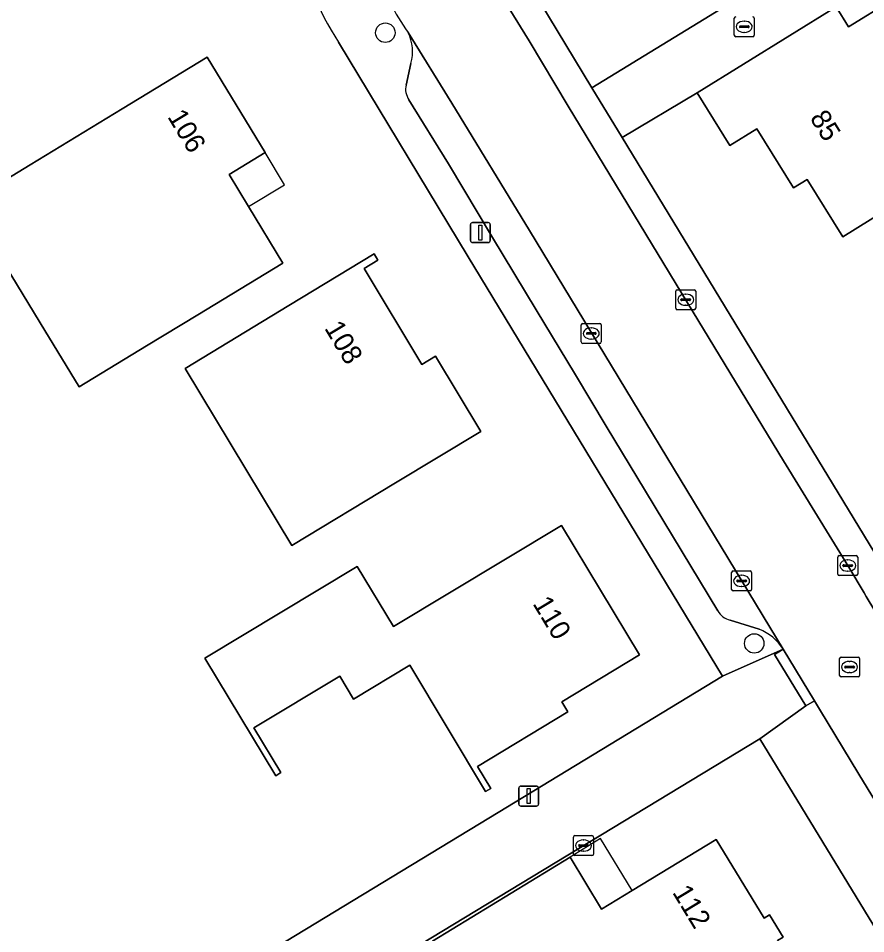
# Model space of a CAD drawing. Extents: x 157767 to 159172, y 387839 to 389425.
# Drawn here: x 158027.91 to 158070.43, y 388633.65 to 388679.57 of the extents above; entities that cross this region are included whole.
import ezdxf

# ---------------------------------------------------------------- set-up
doc = ezdxf.new("R2010")
doc.units = 0
for name, color, linetype in [('IMGEO_Boom', 7, 'Continuous'), ('IMGEO_Erf', 7, 'Continuous'), ('IMGEO_Kolk', 7, 'Continuous'), ('IMGEO_Lichtmast', 7, 'Continuous'), ('IMGEO_Muur', 7, 'Continuous'), ('IMGEO_Pand', 7, 'Continuous'), ('IMGEO_Pand_nummerreeks', 7, 'Continuous'), ('IMGEO_Pand_overbouw', 7, 'Continuous'), ('IMGEO_Parkeervlak_open', 7, 'Continuous'), ('IMGEO_Rijbaan_lokaal_open', 7, 'Continuous'), ('IMGEO_Rioolput', 7, 'Continuous'), ('IMGEO_Voetpad_open', 7, 'Continuous')]:
    doc.layers.add(name, color=color, linetype=linetype)

msp = doc.modelspace()

# ---------------------------------------------------------------- linework, layer by layer
at = {"layer": 'IMGEO_Boom'}
for centre in [(158046.326, 388678.85), (158064.837, 388648.212)]:
    msp.add_circle(centre, 0.489, dxfattribs=at)
at = {"layer": 'IMGEO_Erf'}
for points in [[(158052.773, 388682.571), (158056.692, 388676.089), (158064.654, 388680.973)], [(158068.943, 388680.157), (158069.57, 388679.146), (158073.821, 388681.779), (158076.455, 388677.529), (158077.139, 388676.424), (158076.034, 388675.74), (158077.06, 388674.085), (158076.816, 388673.284), (158073.526, 388671.246), (158069.275, 388668.613), (158067.496, 388671.486), (158066.81, 388671.062), (158064.973, 388674.028), (158063.613, 388673.186), (158061.971, 388675.839), (158058.217, 388673.595), (158071.632, 388651.501), (158075.819, 388644.604), (158080.893, 388635.943)], [(158027.097, 388624.476), (158029.051, 388625.711), (158032.676, 388628.003), (158051.995, 388639.731), (158063.248, 388646.562), (158050.482, 388667.602), (158043.974, 388678.374)], [(158073.538, 388629.633), (158065.111, 388643.432), (158048.605, 388633.424), (158041.934, 388629.381), (158019.422, 388615.682), (158006.062, 388607.391), (158003.544, 388605.795), (158007.121, 388599.66), (158008.464, 388601.21), (158008.786, 388601.467), (158010.188, 388602.586), (158011.828, 388603.703), (158014.005, 388604.812), (158016.147, 388601.216), (158027.188, 388581.174), (158029.267, 388577.665), (158033.868, 388570.534), (158041.859, 388557.406), (158043.338, 388554.813), (158043.765, 388552.918), (158061.703, 388519.687), (158072.331, 388500), (158089.66, 388467.898), (158102.446, 388447.213)]]:
    msp.add_lwpolyline(points, dxfattribs=at)
for points in [[(158037.39, 388677.63), (158040.29, 388672.84), (158038.486, 388671.746), (158039.466, 388670.129), (158041.187, 388667.29), (158036.912, 388664.699), (158034.35, 388663.146), (158030.958, 388661.09), (158029.242, 388663.909), (158025.35, 388670.303), (158028.5, 388672.22), (158033.119, 388675.031)], [(158051.122, 388658.843), (158046.84, 388656.263), (158041.631, 388653.124), (158036.277, 388662.007), (158041.486, 388665.171), (158045.759, 388667.766), (158045.955, 388667.439), (158045.269, 388667.028), (158048.164, 388662.21), (158048.851, 388662.622)], [(158055.159, 388654.135), (158059.082, 388647.632), (158055.181, 388645.285), (158055.488, 388644.772), (158050.953, 388642.044), (158051.617, 388640.94), (158051.36, 388640.786), (158047.552, 388647.116), (158044.729, 388645.417), (158044.038, 388646.563), (158039.735, 388643.974), (158041.083, 388641.732), (158040.826, 388641.577), (158037.274, 388647.48), (158044.921, 388652.079), (158046.732, 388649.068)], [(158051.48, 388628.668), (158051.278, 388629.002), (158048.692, 388633.28), (158055.594, 388637.493), (158057.18, 388634.883), (158058.716, 388635.816), (158062.929, 388638.376), (158065.328, 388634.427), (158065.602, 388634.594), (158066.281, 388633.476), (158066.009, 388633.312), (158066.589, 388632.357), (158062.319, 388629.758), (158057.749, 388626.976), (158055.323, 388630.99)]]:
    msp.add_lwpolyline(points, close=True, dxfattribs=at)
msp.add_arc((158058.394, 388687.505), 17.068, 174.4587, 212.3421, dxfattribs=at)
at = {"layer": 'IMGEO_Kolk'}
for p, q in [((158063.835, 388678.722), (158063.835, 388679.574)), ((158064.836, 388679.574), (158064.836, 388678.722)), ((158064.094, 388679.142), (158064.094, 388679.154)), ((158064.532, 388679.105), (158064.134, 388679.105)), ((158064.137, 388679.191), (158064.535, 388679.191)), ((158064.323, 388679.428), (158064.348, 388679.428)), ((158064.578, 388679.154), (158064.578, 388679.142)), ((158064.762, 388678.648), (158063.91, 388678.648)), ((158064.346, 388678.868), (158064.321, 388678.868)), ((158060.899, 388665.029), (158060.899, 388665.881)), ((158060.974, 388665.955), (158061.826, 388665.955)), ((158061.387, 388665.735), (158061.412, 388665.735)), ((158061.9, 388665.881), (158061.9, 388665.029)), ((158061.158, 388665.449), (158061.158, 388665.461)), ((158061.596, 388665.412), (158061.198, 388665.412)), ((158061.201, 388665.498), (158061.599, 388665.498)), ((158061.642, 388665.461), (158061.642, 388665.449)), ((158061.826, 388664.955), (158060.974, 388664.955)), ((158061.41, 388665.175), (158061.385, 388665.175)), ((158056.159, 388663.336), (158056.159, 388664.188)), ((158056.234, 388664.262), (158057.086, 388664.262)), ((158056.647, 388664.042), (158056.672, 388664.042)), ((158057.16, 388664.188), (158057.16, 388663.336)), ((158056.418, 388663.756), (158056.418, 388663.768)), ((158056.856, 388663.719), (158056.458, 388663.719)), ((158056.461, 388663.805), (158056.859, 388663.805)), ((158056.67, 388663.482), (158056.645, 388663.482)), ((158056.902, 388663.768), (158056.902, 388663.756)), ((158057.086, 388663.262), (158056.234, 388663.262)), ((158069.027, 388651.692), (158069.027, 388652.544)), ((158069.102, 388652.618), (158069.954, 388652.618)), ((158069.515, 388652.398), (158069.54, 388652.398)), ((158070.028, 388652.544), (158070.028, 388651.692)), ((158069.286, 388652.112), (158069.286, 388652.124)), ((158069.724, 388652.075), (158069.326, 388652.075)), ((158069.329, 388652.161), (158069.727, 388652.161)), ((158069.77, 388652.124), (158069.77, 388652.112)), ((158063.702, 388650.923), (158063.702, 388651.775)), ((158063.777, 388651.849), (158064.629, 388651.849)), ((158064.19, 388651.629), (158064.215, 388651.629)), ((158064.703, 388651.775), (158064.703, 388650.923)), ((158069.954, 388651.618), (158069.102, 388651.618)), ((158069.538, 388651.838), (158069.513, 388651.838)), ((158063.961, 388651.343), (158063.961, 388651.355)), ((158064.399, 388651.306), (158064.001, 388651.306)), ((158064.004, 388651.392), (158064.402, 388651.392)), ((158064.213, 388651.069), (158064.188, 388651.069)), ((158064.445, 388651.355), (158064.445, 388651.343)), ((158064.629, 388650.849), (158063.777, 388650.849)), ((158055.768, 388637.646), (158055.768, 388638.498)), ((158055.843, 388638.572), (158056.695, 388638.572)), ((158056.256, 388638.352), (158056.281, 388638.352)), ((158056.769, 388638.498), (158056.769, 388637.646)), ((158056.027, 388638.066), (158056.027, 388638.078)), ((158056.465, 388638.029), (158056.067, 388638.029)), ((158056.07, 388638.115), (158056.468, 388638.115)), ((158056.279, 388637.792), (158056.254, 388637.792)), ((158056.511, 388638.078), (158056.511, 388638.066)), ((158056.695, 388637.572), (158055.843, 388637.572))]:
    msp.add_line(p, q, dxfattribs=at)
for points in [[(158063.835, 388678.722), (158063.835, 388679.574)], [(158064.836, 388679.574), (158064.836, 388678.722)], [(158064.762, 388678.648), (158063.91, 388678.648)], [(158060.899, 388665.029), (158060.899, 388665.881)], [(158060.974, 388665.955), (158061.826, 388665.955)], [(158061.9, 388665.881), (158061.9, 388665.029)], [(158061.826, 388664.955), (158060.974, 388664.955)], [(158056.159, 388663.336), (158056.159, 388664.188)], [(158056.234, 388664.262), (158057.086, 388664.262)], [(158057.16, 388664.188), (158057.16, 388663.336)], [(158057.086, 388663.262), (158056.234, 388663.262)], [(158069.027, 388651.692), (158069.027, 388652.544)], [(158069.102, 388652.618), (158069.954, 388652.618)], [(158070.028, 388652.544), (158070.028, 388651.692)], [(158063.702, 388650.923), (158063.702, 388651.775)], [(158063.777, 388651.849), (158064.629, 388651.849)], [(158064.703, 388651.775), (158064.703, 388650.923)], [(158069.954, 388651.618), (158069.102, 388651.618)], [(158064.629, 388650.849), (158063.777, 388650.849)], [(158055.768, 388637.646), (158055.768, 388638.498)], [(158055.843, 388638.572), (158056.695, 388638.572)], [(158056.769, 388638.498), (158056.769, 388637.646)], [(158056.695, 388637.572), (158055.843, 388637.572)]]:
    msp.add_lwpolyline(points, dxfattribs=at)
for centre, radius, start, end in [((158063.912, 388679.572), 0.0765, 91.552, 178.448), ((158063.912, 388679.572), 0.0765, 91.552, 178.448), ((158064.76, 388679.572), 0.0765, 1.552, 88.448), ((158064.76, 388679.572), 0.0765, 1.552, 88.448), ((158064.134, 388679.151), 0.0403, 85.8775, 175.7526), ((158064.131, 388679.141), 0.0366, 178.938, 274.7102), ((158064.535, 388679.148), 0.043, 264.8664, 352.4533), ((158064.539, 388679.153), 0.0386, 1.7309, 96.639), ((158063.912, 388678.724), 0.0765, 181.552, 268.448), ((158063.912, 388678.724), 0.0765, 181.552, 268.448), ((158064.76, 388678.724), 0.0765, 271.552, 358.448), ((158064.76, 388678.724), 0.0765, 271.552, 358.448), ((158060.976, 388665.879), 0.0765, 91.552, 178.448), ((158060.976, 388665.879), 0.0765, 91.552, 178.448), ((158061.824, 388665.879), 0.0765, 1.552, 88.448), ((158061.824, 388665.879), 0.0765, 1.552, 88.448), ((158061.198, 388665.458), 0.0403, 85.8775, 175.7526), ((158061.195, 388665.448), 0.0366, 178.938, 274.7102), ((158061.599, 388665.455), 0.043, 264.8664, 352.4533), ((158061.603, 388665.46), 0.0386, 1.7309, 96.639), ((158060.976, 388665.031), 0.0765, 181.552, 268.448), ((158060.976, 388665.031), 0.0765, 181.552, 268.448), ((158061.824, 388665.031), 0.0765, 271.552, 358.448), ((158061.824, 388665.031), 0.0765, 271.552, 358.448), ((158056.236, 388664.186), 0.0765, 91.552, 178.448), ((158056.236, 388664.186), 0.0765, 91.552, 178.448), ((158057.084, 388664.186), 0.0765, 1.552, 88.448), ((158057.084, 388664.186), 0.0765, 1.552, 88.448), ((158056.458, 388663.765), 0.0403, 85.8775, 175.7526), ((158056.455, 388663.755), 0.0366, 178.938, 274.7102), ((158056.859, 388663.762), 0.043, 264.8664, 352.4533), ((158056.863, 388663.767), 0.0386, 1.7309, 96.639), ((158056.236, 388663.338), 0.0765, 181.552, 268.448), ((158056.236, 388663.338), 0.0765, 181.552, 268.448), ((158057.084, 388663.338), 0.0765, 271.552, 358.448), ((158057.084, 388663.338), 0.0765, 271.552, 358.448), ((158069.104, 388652.542), 0.0765, 91.552, 178.448), ((158069.104, 388652.542), 0.0765, 91.552, 178.448), ((158069.952, 388652.542), 0.0765, 1.552, 88.448), ((158069.952, 388652.542), 0.0765, 1.552, 88.448), ((158069.326, 388652.121), 0.0403, 85.8775, 175.7526), ((158069.323, 388652.111), 0.0366, 178.938, 274.7102), ((158069.727, 388652.118), 0.043, 264.8664, 352.4533), ((158069.731, 388652.123), 0.0386, 1.7309, 96.639), ((158063.779, 388651.773), 0.0765, 91.552, 178.448), ((158063.779, 388651.773), 0.0765, 91.552, 178.448), ((158064.627, 388651.773), 0.0765, 1.552, 88.448), ((158064.627, 388651.773), 0.0765, 1.552, 88.448), ((158069.104, 388651.694), 0.0765, 181.552, 268.448), ((158069.104, 388651.694), 0.0765, 181.552, 268.448), ((158069.952, 388651.694), 0.0765, 271.552, 358.448), ((158069.952, 388651.694), 0.0765, 271.552, 358.448), ((158064.001, 388651.352), 0.0403, 85.8775, 175.7526), ((158063.998, 388651.342), 0.0366, 178.938, 274.7102), ((158064.402, 388651.349), 0.043, 264.8664, 352.4533), ((158064.406, 388651.354), 0.0386, 1.7309, 96.639), ((158063.779, 388650.925), 0.0765, 181.552, 268.448), ((158063.779, 388650.925), 0.0765, 181.552, 268.448), ((158064.627, 388650.925), 0.0765, 271.552, 358.448), ((158064.627, 388650.925), 0.0765, 271.552, 358.448), ((158055.845, 388638.496), 0.0765, 91.552, 178.448), ((158055.845, 388638.496), 0.0765, 91.552, 178.448), ((158056.693, 388638.496), 0.0765, 1.552, 88.448), ((158056.693, 388638.496), 0.0765, 1.552, 88.448), ((158056.067, 388638.075), 0.0403, 85.8775, 175.7526), ((158056.064, 388638.065), 0.0366, 178.938, 274.7102), ((158056.468, 388638.072), 0.043, 264.8664, 352.4533), ((158056.472, 388638.077), 0.0386, 1.7309, 96.639), ((158055.845, 388637.648), 0.0765, 181.552, 268.448), ((158055.845, 388637.648), 0.0765, 181.552, 268.448), ((158056.693, 388637.648), 0.0765, 271.552, 358.448), ((158056.693, 388637.648), 0.0765, 271.552, 358.448)]:
    msp.add_arc(centre, radius, start, end, dxfattribs=at)
for centre, major_axis, ratio, start_param, end_param in [((158064.322, 388679.148), (-0.387, 0.002), 0.722429, 4.712389, 7.853982), ((158064.347, 388679.148), (-0.39, 0.002), 0.717154, 1.570796, 4.712389), ((158061.386, 388665.455), (-0.387, 0.002), 0.722429, 4.712389, 7.853982), ((158061.411, 388665.455), (-0.39, 0.002), 0.717154, 1.570796, 4.712389), ((158056.646, 388663.762), (-0.387, 0.002), 0.722429, 4.712389, 7.853982), ((158056.671, 388663.762), (-0.39, 0.002), 0.717154, 1.570796, 4.712389), ((158069.514, 388652.118), (-0.387, 0.002), 0.722429, 4.712389, 7.853982), ((158069.539, 388652.118), (-0.39, 0.002), 0.717154, 1.570796, 4.712389), ((158064.189, 388651.349), (-0.387, 0.002), 0.722429, 4.712389, 7.853982), ((158064.214, 388651.349), (-0.39, 0.002), 0.717154, 1.570796, 4.712389), ((158056.255, 388638.072), (-0.387, 0.002), 0.722429, 4.712389, 7.853982), ((158056.28, 388638.072), (-0.39, 0.002), 0.717154, 1.570796, 4.712389)]:
    msp.add_ellipse(centre, major_axis=major_axis, ratio=ratio, start_param=start_param, end_param=end_param, dxfattribs=at)
at = {"layer": 'IMGEO_Lichtmast'}
for p, q in [((158050.6, 388668.423), (158050.6, 388669.223)), ((158050.6, 388669.223), (158050.6, 388668.423)), ((158050.7, 388669.323), (158051.49, 388669.323)), ((158051.49, 388669.323), (158050.7, 388669.323)), ((158051.59, 388669.223), (158051.59, 388668.423)), ((158051.59, 388668.423), (158051.59, 388669.223)), ((158051.49, 388668.323), (158050.7, 388668.323)), ((158050.7, 388668.323), (158051.49, 388668.323)), ((158053.023, 388640.153), (158053.023, 388640.953)), ((158053.023, 388640.953), (158053.023, 388640.153)), ((158053.123, 388641.053), (158053.913, 388641.053)), ((158053.913, 388641.053), (158053.123, 388641.053)), ((158054.013, 388640.953), (158054.013, 388640.153)), ((158054.013, 388640.153), (158054.013, 388640.953)), ((158053.913, 388640.053), (158053.123, 388640.053)), ((158053.123, 388640.053), (158053.913, 388640.053))]:
    msp.add_line(p, q, dxfattribs=at)
for points in [[(158051.02, 388669.198), (158051.17, 388669.198), (158051.17, 388668.448), (158051.02, 388668.448), (158051.02, 388669.198)], [(158053.443, 388640.928), (158053.593, 388640.928), (158053.593, 388640.178), (158053.443, 388640.178), (158053.443, 388640.928)]]:
    msp.add_lwpolyline(points, dxfattribs=at)
for centre, start, end in [((158050.7, 388669.223), 90, 180), ((158050.7, 388669.223), 90, 180), ((158051.49, 388669.223), 0, 90), ((158051.49, 388669.223), 360, 90), ((158050.7, 388668.423), 180, 270), ((158050.7, 388668.423), 180, 270), ((158051.49, 388668.423), 270, 0), ((158051.49, 388668.423), 270, 0), ((158053.123, 388640.953), 90, 180), ((158053.123, 388640.953), 90, 180), ((158053.913, 388640.953), 0, 90), ((158053.913, 388640.953), 360, 90), ((158053.123, 388640.153), 180, 270), ((158053.123, 388640.153), 180, 270), ((158053.913, 388640.153), 270, 0), ((158053.913, 388640.153), 270, 0)]:
    msp.add_arc(centre, 0.1, start, end, dxfattribs=at)
at = {"layer": 'IMGEO_Muur'}
msp.add_lwpolyline([(158032.676, 388628.003), (158051.995, 388639.731)], dxfattribs=at)
at = {"layer": 'IMGEO_Pand'}
for points in [[(158076.034, 388675.74), (158077.139, 388676.424), (158076.455, 388677.529), (158073.821, 388681.779), (158069.57, 388679.146), (158068.943, 388680.157), (158061.971, 388675.839), (158063.613, 388673.186), (158064.973, 388674.028), (158066.81, 388671.062), (158067.496, 388671.486), (158069.275, 388668.613), (158073.526, 388671.246), (158076.816, 388673.284), (158077.06, 388674.085)], [(158039.466, 388670.129), (158038.486, 388671.746), (158040.29, 388672.84), (158037.39, 388677.63), (158033.119, 388675.031), (158028.5, 388672.22), (158025.35, 388670.303), (158029.242, 388663.909), (158030.958, 388661.09), (158034.35, 388663.146), (158036.912, 388664.699), (158041.187, 388667.29)], [(158046.84, 388656.263), (158051.122, 388658.843), (158048.851, 388662.622), (158048.164, 388662.21), (158045.269, 388667.028), (158045.955, 388667.439), (158045.759, 388667.766), (158041.486, 388665.171), (158036.277, 388662.007), (158041.631, 388653.124)], [(158051.36, 388640.786), (158051.617, 388640.94), (158050.953, 388642.044), (158055.488, 388644.772), (158055.181, 388645.285), (158059.082, 388647.632), (158055.159, 388654.135), (158046.732, 388649.068), (158044.921, 388652.079), (158037.274, 388647.48), (158040.826, 388641.577), (158041.083, 388641.732), (158039.735, 388643.974), (158044.038, 388646.563), (158044.729, 388645.417), (158047.552, 388647.116)], [(158055.594, 388637.493), (158048.692, 388633.28), (158051.278, 388629.002), (158051.48, 388628.668), (158055.323, 388630.99), (158057.749, 388626.976), (158062.319, 388629.758), (158066.589, 388632.357), (158066.009, 388633.312), (158066.281, 388633.476), (158065.602, 388634.594), (158065.328, 388634.427), (158062.929, 388638.376), (158058.716, 388635.816), (158057.18, 388634.883)]]:
    msp.add_lwpolyline(points, close=True, dxfattribs=at)
at = {"layer": 'IMGEO_Pand_overbouw'}
for points in [[(158040.29, 388672.84), (158038.486, 388671.746), (158039.466, 388670.129), (158041.269, 388671.223)], [(158055.594, 388637.493), (158057.18, 388634.883), (158058.716, 388635.816), (158057.129, 388638.43)]]:
    msp.add_lwpolyline(points, close=True, dxfattribs=at)
at = {"layer": 'IMGEO_Parkeervlak_open'}
for points in [[(158066.288, 388647.922), (158053.554, 388668.935), (158049.671, 388675.314), (158047.465, 388678.857)], [(158047.603, 388677.313), (158047.366, 388676.227)], [(158047.505, 388675.491), (158049.499, 388672.271), (158051.705, 388668.578), (158053.898, 388664.943), (158055.866, 388661.679), (158057.413, 388659.115), (158059.378, 388655.857), (158063.006, 388649.843)], [(158063.629, 388649.386), (158065.086, 388648.93)]]:
    msp.add_lwpolyline(points, dxfattribs=at)
for centre, radius, start, end in [((158045.65, 388677.917), 2.044, 342.825, 27.3898), ((158048.295, 388676.021), 0.952, 167.5208, 213.8689), ((158063.82, 388650.3), 0.933, 209.2874, 258.1889), ((158064.078, 388646.507), 2.624, 32.6243, 67.4092)]:
    msp.add_arc(centre, radius, start, end, dxfattribs=at)
at = {"layer": 'IMGEO_Rijbaan_lokaal_open'}
for points in [[(158079.479, 388635.466), (158074.539, 388643.81), (158072.431, 388647.303), (158070.457, 388650.573), (158070.352, 388650.747), (158069.575, 388652.039), (158066.309, 388657.375), (158061.493, 388665.301), (158055.506, 388675.171), (158053.536, 388678.444), (158051.319, 388682.056)], [(158047.465, 388678.857), (158049.671, 388675.314), (158053.554, 388668.935), (158066.288, 388647.922), (158067.854, 388645.332), (158068.111, 388644.907), (158070.083, 388641.645), (158073.98, 388635.256), (158076.366, 388631.359), (158080.427, 388633.957)]]:
    msp.add_lwpolyline(points, dxfattribs=at)
msp.add_arc((158058.606, 388686.516), 13.52, 199.5549, 214.5074, dxfattribs=at)
at = {"layer": 'IMGEO_Rioolput'}
for p, q in [((158069.117, 388646.602), (158069.117, 388647.454)), ((158069.192, 388647.528), (158070.044, 388647.528)), ((158069.605, 388647.308), (158069.63, 388647.308)), ((158070.118, 388647.454), (158070.118, 388646.602)), ((158069.376, 388647.022), (158069.376, 388647.034)), ((158069.814, 388646.985), (158069.416, 388646.985)), ((158069.419, 388647.071), (158069.817, 388647.071)), ((158069.86, 388647.034), (158069.86, 388647.022)), ((158070.044, 388646.528), (158069.192, 388646.528)), ((158069.628, 388646.748), (158069.603, 388646.748))]:
    msp.add_line(p, q, dxfattribs=at)
for points in [[(158069.117, 388646.602), (158069.117, 388647.454)], [(158069.192, 388647.528), (158070.044, 388647.528)], [(158070.118, 388647.454), (158070.118, 388646.602)], [(158070.044, 388646.528), (158069.192, 388646.528)]]:
    msp.add_lwpolyline(points, dxfattribs=at)
for centre, radius, start, end in [((158069.194, 388647.452), 0.0765, 91.552, 178.448), ((158069.194, 388647.452), 0.0765, 91.552, 178.448), ((158070.042, 388647.452), 0.0765, 1.552, 88.448), ((158070.042, 388647.452), 0.0765, 1.552, 88.448), ((158069.416, 388647.031), 0.0403, 85.8775, 175.7526), ((158069.413, 388647.021), 0.0366, 178.938, 274.7102), ((158069.817, 388647.028), 0.043, 264.8664, 352.4533), ((158069.821, 388647.033), 0.0386, 1.7309, 96.639), ((158069.194, 388646.604), 0.0765, 181.552, 268.448), ((158069.194, 388646.604), 0.0765, 181.552, 268.448), ((158070.042, 388646.604), 0.0765, 271.552, 358.448), ((158070.042, 388646.604), 0.0765, 271.552, 358.448)]:
    msp.add_arc(centre, radius, start, end, dxfattribs=at)
for centre, major_axis, ratio, start_param, end_param in [((158069.604, 388647.028), (-0.387, 0.002), 0.722429, 4.712389, 7.853982), ((158069.629, 388647.028), (-0.39, 0.002), 0.717154, 1.570796, 4.712389)]:
    msp.add_ellipse(centre, major_axis=major_axis, ratio=ratio, start_param=start_param, end_param=end_param, dxfattribs=at)
at = {"layer": 'IMGEO_Voetpad_open'}
for points in [[(158098.704, 388694.959), (158098.771, 388694.795), (158124.506, 388705.952), (158134.614, 388710.329), (158136.456, 388711.226), (158134.627, 388711.957), (158124.222, 388707.486), (158090.25, 388692.79), (158089.145, 388695.349), (158085.544, 388693.809), (158080.844, 388690.903), (158064.654, 388680.973), (158056.692, 388676.089), (158058.217, 388673.595), (158061.971, 388675.839), (158068.943, 388680.157), (158078.988, 388686.371), (158081.65, 388687.48), (158085.01, 388688.91)], [(158041.934, 388629.381), (158048.605, 388633.424), (158065.111, 388643.432), (158067.431, 388645.075), (158065.861, 388647.663), (158066.288, 388647.922), (158063.248, 388646.562), (158051.995, 388639.731), (158032.676, 388628.003), (158029.051, 388625.711), (158027.097, 388624.476), (158026.997, 388624.413), (158022.773, 388621.743), (158018.046, 388618.755), (158007.621, 388612.401), (158004.78, 388610.757), (158004.362, 388610.562), (158004.038, 388610.411), (158003.231, 388610.223), (158002.467, 388610.25), (158000.914, 388610.672), (158003.544, 388605.795), (158006.062, 388607.391), (158019.422, 388615.682)], [(158066.288, 388647.922), (158065.861, 388647.663), (158067.431, 388645.075), (158067.854, 388645.332)]]:
    msp.add_lwpolyline(points, close=True, dxfattribs=at)
for points in [[(158080.893, 388635.943), (158075.819, 388644.604), (158071.632, 388651.501), (158058.217, 388673.595), (158056.692, 388676.089), (158052.773, 388682.571)], [(158051.319, 388682.056), (158053.536, 388678.444), (158055.506, 388675.171), (158061.493, 388665.301), (158066.309, 388657.375), (158069.575, 388652.039), (158070.352, 388650.747), (158070.457, 388650.573), (158072.431, 388647.303), (158074.539, 388643.81), (158079.479, 388635.466)], [(158043.974, 388678.374), (158050.482, 388667.602), (158063.248, 388646.562), (158066.288, 388647.922)], [(158047.366, 388676.227), (158047.603, 388677.313)], [(158063.006, 388649.843), (158059.378, 388655.857), (158057.413, 388659.115), (158055.866, 388661.679), (158053.898, 388664.943), (158051.705, 388668.578), (158049.499, 388672.271), (158047.505, 388675.491)], [(158065.086, 388648.93), (158063.629, 388649.386)], [(158076.366, 388631.359), (158073.98, 388635.256), (158070.083, 388641.645), (158068.111, 388644.907), (158067.854, 388645.332), (158067.431, 388645.075), (158065.111, 388643.432), (158073.538, 388629.633)]]:
    msp.add_lwpolyline(points, dxfattribs=at)
for centre, radius, start, end in [((158058.394, 388687.505), 17.068, 174.4587, 212.3421), ((158058.606, 388686.516), 13.52, 199.5549, 214.5074), ((158045.65, 388677.917), 2.044, 342.825, 27.3898), ((158048.295, 388676.021), 0.952, 167.5208, 213.8689), ((158063.82, 388650.3), 0.933, 209.2874, 258.1889), ((158064.078, 388646.507), 2.624, 32.6243, 67.4092)]:
    msp.add_arc(centre, radius, start, end, dxfattribs=at)

# ---------------------------------------------------------------- texts
at = {"layer": 'IMGEO_Pand_nummerreeks'}
for s, rotation, p in [('106', 301.1916, (158035.368, 388674.638)), ('85', 301.7703, (158067.599, 388674.575)), ('108', 301.0005, (158043.244, 388664.03)), ('110', 301.1009, (158053.695, 388650.211)), ('112', 301.2785, (158060.703, 388635.723))]:
    msp.add_text(s, height=1, rotation=rotation, dxfattribs=at).set_placement(p)

doc.saveas('drawing.dxf')
